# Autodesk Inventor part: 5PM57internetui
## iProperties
Created: 2010-11
Part Number: 5PM57internetui
Document SubType Name: Modeling
Designer: Darius
Author: Darius
Translation Standard: STEP AP203
File Name: 5PM57.STEP
Preprocessor: SolidWorks 2003240
Postprocessor: Build: 272, Release: 10 SP3a - Date: Thu 12/15/2005
Sent Units: MILLIMETERS
Uncertainty: 1e-05
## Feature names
1. Base1
